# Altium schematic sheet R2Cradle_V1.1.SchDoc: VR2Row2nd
size A3; Revision: V.A; SheetNumber: 1; SheetTotal: 1; Date: 11/13/2023; Engineer: 周松; PageSetup: Record=PageOptions¦CenterHorizontal=True¦CenterVertical=True¦PrintScale=1.04¦XCorrection=1.00¦YCorrection=1.00¦PrintKind=0¦BorderSize=5000000¦LeftOffset=0¦BottomOffset=0¦Orientation=2¦PaperLength=1000¦PaperWidth=1000¦Scale=100¦PaperSource=7¦PrintQuality=-4¦MediaType=1¦DitherType=10¦PaperKind=A3¦PrintScaleMode=1
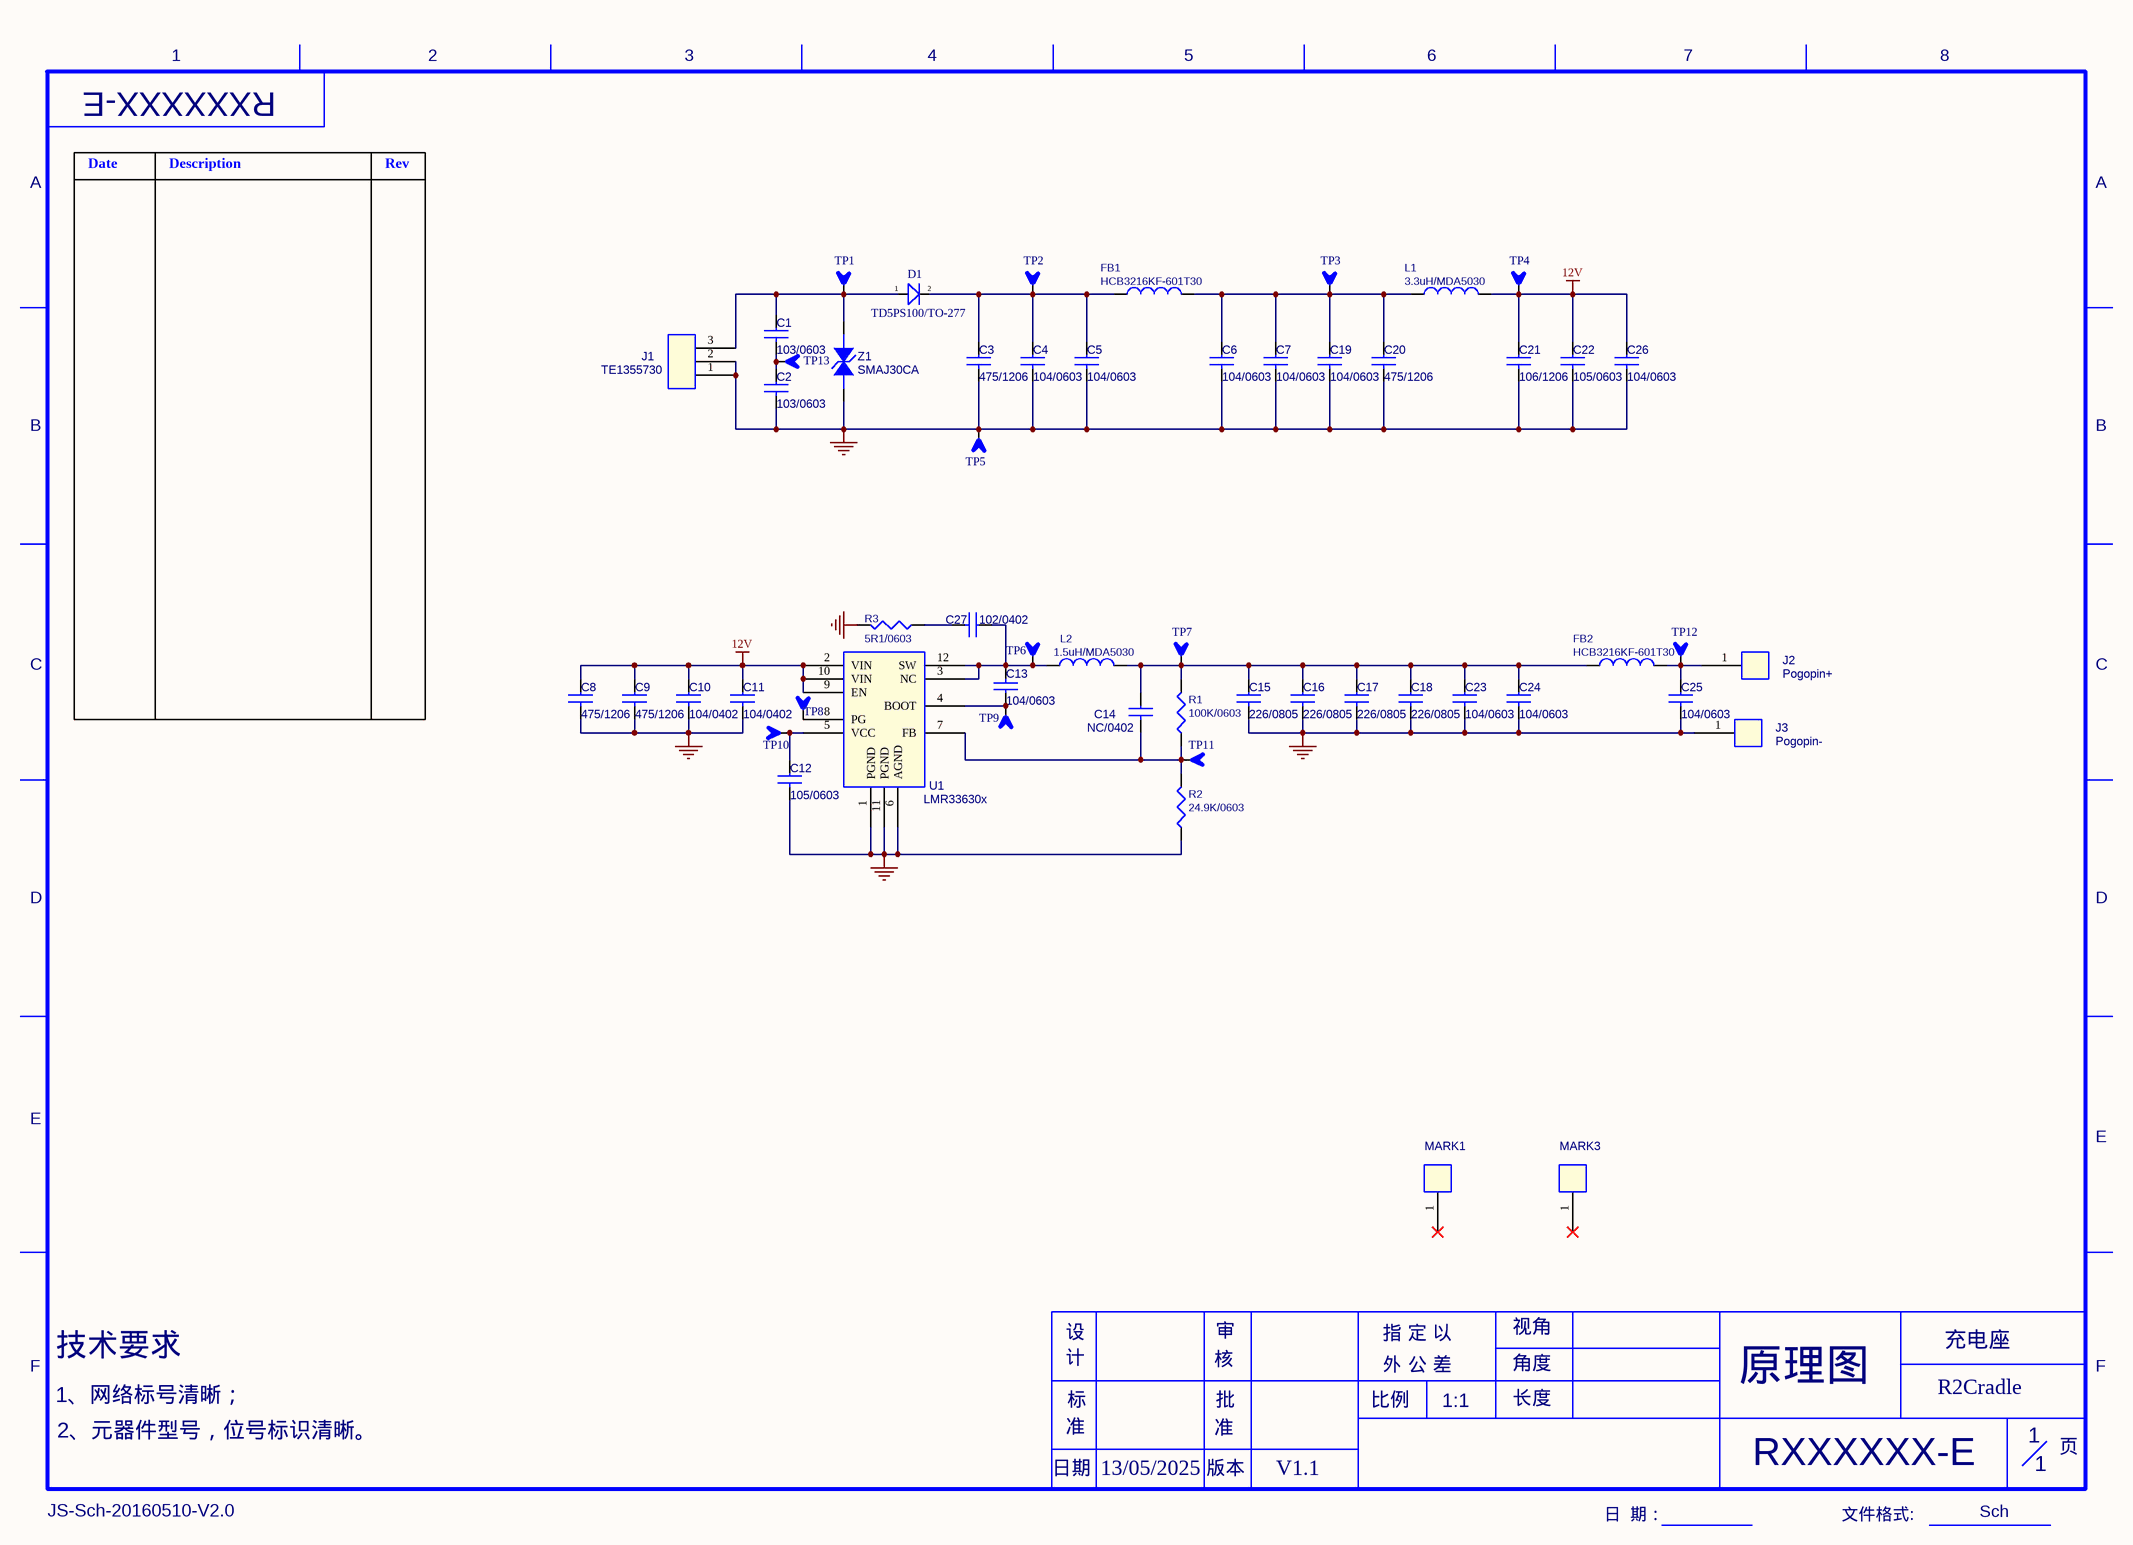
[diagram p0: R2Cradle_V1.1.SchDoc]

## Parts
C1  value 103/0603  [RC0603]  (hidden comment: CAP NP)
C2  value 103/0603  [RC0603]  (hidden comment: CAP NP)
C3  value 475/1206  [RC1206]  (hidden comment: CAP NP)
C4  value 104/0603  [RC0603]  (hidden comment: CAP NP)
C5  value 104/0603  [RC0603]  (hidden comment: CAP NP)
C6  value 104/0603  [RC0603]  (hidden comment: CAP NP)
C7  value 104/0603  [RC0603]  (hidden comment: CAP NP)
C8  value 475/1206  [RC1206]  (hidden comment: CAP NP)
C9  value 475/1206  [RC1206]  (hidden comment: CAP NP)
C10  value 104/0402  [C0402]  (hidden comment: Comment)
C11  value 104/0402  [C0402]  (hidden comment: Comment)
C12  value 105/0603  [RC0603]  (hidden comment: CAP NP)
C13  value 104/0603  [RC0603]  (hidden comment: CAP NP)
C14  value NC/0402  [C0402]  (hidden comment: Comment)
C15  value 226/0805  [RC0805]  (hidden comment: CAP NP)
C16  value 226/0805  [RC0805]  (hidden comment: CAP NP)
C17  value 226/0805  [RC0805]  (hidden comment: CAP NP)
C18  value 226/0805  [RC0805]  (hidden comment: CAP NP)
C19  value 104/0603  [RC1206]  (hidden comment: CAP NP)
C20  value 475/1206  [RC1206]  (hidden comment: CAP NP)
C21  value 106/1206  [RC1206]  (hidden comment: CAP NP)
C22  value 105/0603  [RC0603]  (hidden comment: CAP NP)
C23  value 104/0603  [RC0603]  (hidden comment: CAP NP)
C24  value 104/0603  [RC0603]  (hidden comment: NC)
C25  value 104/0603  [RC0603]  (hidden comment: NC)
C26  value 104/0603  [RC0603]  (hidden comment: NC)
C27  value 102/0402  [RC0603]  (hidden comment: NC)
D1  TD5PS100/TO-277  [DPOW]
FB1  value HCB3216KF-601T30  [N1206]  (hidden comment: Comment)
FB2  value HCB3216KF-601T30  [N1206]  (hidden comment: Comment)
J1  value TE1355730  [TE1355730-B]  (hidden comment: CON3)
J2  value Pogopin+  [pogopin]  (hidden comment: CON1)
J3  value Pogopin-  [pogopin]  (hidden comment: CON1)
L1  value 3.3uH/MDA5030  [MDA5030]  (hidden comment: INDUCTOR)
L2  value 1.5uH/MDA5030  [MDA5030]  (hidden comment: INDUCTOR)
MARK1  CON1  [MARK_2_0]  (value not drawn)
MARK3  CON1  [MARK_2_0]  (value not drawn)
R1  value 100K/0603  [RC0603]  (hidden comment: R)
R2  value 24.9K/0603  [RC0603]  (hidden comment: R)
R3  value 5R1/0603  [RC0603]  (hidden comment: R)
TP1  TP  [MARK_13]  (value not drawn)
TP2  TP  [MARK_13]  (value not drawn)
TP3  TP  [MARK_13]  (value not drawn)
TP4  TP  [MARK_13]  (value not drawn)
TP5  TP  [MARK_13]  (value not drawn)
TP6  TP  [MARK_13]  (value not drawn)
TP7  TP  [MARK_13]  (value not drawn)
TP8  TP  [MARK_13]  (value not drawn)
TP9  TP  [MARK_13]  (value not drawn)
TP10  TP  [MARK_13]  (value not drawn)
TP11  TP  [MARK_13]  (value not drawn)
TP12  TP  [MARK_13]  (value not drawn)
TP13  TP  [MARK_13]  (value not drawn)
U1  value LMR33630x  [VQFN12]  (hidden comment: Comment)
Z1  value SMAJ30CA  [SMA]  (hidden comment: TVSbi)

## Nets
12V: C8.1 C9.1 C10.1 C11.1 C21.1 C22.1 C26.1 L1.2 TP4.1 U1.2(VIN) U1.9(EN) U1.10(VIN)
GND_POWER: C2.2 C3.2 C4.2 C5.2 C6.2 C7.2 C8.2 C9.2 C10.2 C11.2 C12.2 C15.2 C16.2 C17.2 C18.2 C19.2 C20.2 C21.2 C22.2 C23.2 C24.1 C25.2 C26.2 J1.1 J1.2 J3.1 R2.1 R3.2 TP5.1 U1.1(PGND) U1.6(AGND) U1.11(PGND) Z1.2
NetC1_1: C1.1 D1.1(A) J1.3 TP1.1 Z1.1
NetC1_2: C1.2 C2.1 TP13.1
NetC3_1: C3.1 C4.1 C5.1 D1.2(K) FB1.1 TP2.1
NetC6_1: C6.1 C7.1 C19.1 C20.1 FB1.2 L1.1 TP3.1
NetC12_1: C12.1 TP10.1 U1.5(VCC)
NetC13_1: C13.1 TP9.1 U1.4(BOOT)
NetC13_2: C13.2 C27.1 L2.1 TP6.1 U1.3(NC) U1.12(SW)
NetC14_1: C14.1 C15.1 C16.1 C17.1 C18.1 C23.1 C24.1 FB2.1 L2.2 R1.2 TP7.1
NetC14_2: C14.2 R1.1 R2.2 TP11.1 U1.7(FB)
NetC25_1: C25.1 FB2.2 J2.1 TP12.1
NetC27_2: C27.2 R3.1
NetTP8_1: TP8.1 U1.8(PG)

Not connected (* = marked no-connect by the designer): MARK1 1*; MARK3 1*

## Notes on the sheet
- 1
- 2
- 3
- 4
- 5
- 6
- 7
- 8
- RXXXXXX-E
- A
- Date
- Description
- Rev
- B
- C
- D
- E
- 设
- 审
- 指 定 以
- 视角
- 充电座
- F
- 技术要求
- 1、网络标号清晰；
- 计
- 标
- 核
- 批
- 比例
- 外 公 差
- 1:1
- 长度
- 角度
- 原理图
- R2Cradle
- 2、元器件型号，位号标识清晰。
- 日期
- 准
- 13/05/2025
- 版本
- V1.1
- 页
- JS-Sch-20160510-V2.0
- 日  期：
- 文件格式:
- Sch

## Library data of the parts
C1 = CAP NP: Part Reference: C1
C2 = CAP NP: Part Reference: C2
C3 = CAP NP: Part Reference: C4
C4 C5 C7 C22-C27 = CAP NP: Part Reference: C3
C6 = CAP NP: Part Reference: C6
C8 C21 = CAP NP: Part Reference: C8
C9 = CAP NP: Part Reference: C9
C10 = CAP NP: Part Reference: C10
C11 = CAP NP: Part Reference: C11
C12 = CAP NP: Part Reference: C12
C13 = CAP NP: Part Reference: C13
C14 = CAP NP: Part Reference: C14
C15 = CAP NP: Part Reference: C15
C16 = CAP NP: Part Reference: C16
C17 = CAP NP: Part Reference: C17
C18 = CAP NP: Part Reference: C18
C19 = CAP NP: Part Reference: C5
C20 = CAP NP: Part Reference: C7
D1 = D1
FB1 FB2 = INDUCTOR: Part Reference: FB1
J1 = CON3: Part Reference: J1
J2 MARK1 MARK3 = CON1: Part Reference: J2
J3 = CON1: Part Reference: J3
L1 = INDUCTOR: Part Reference: L1
L2 = INDUCTOR: Part Reference: L2
R1 R3 = R: Part Reference: R3
R2 = R: Part Reference: R4
U1 = LMR33630x: Part Reference: U1; PCB Footprint: VQFN_HR12
Z1 = TVSbi: Part Reference: Z1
